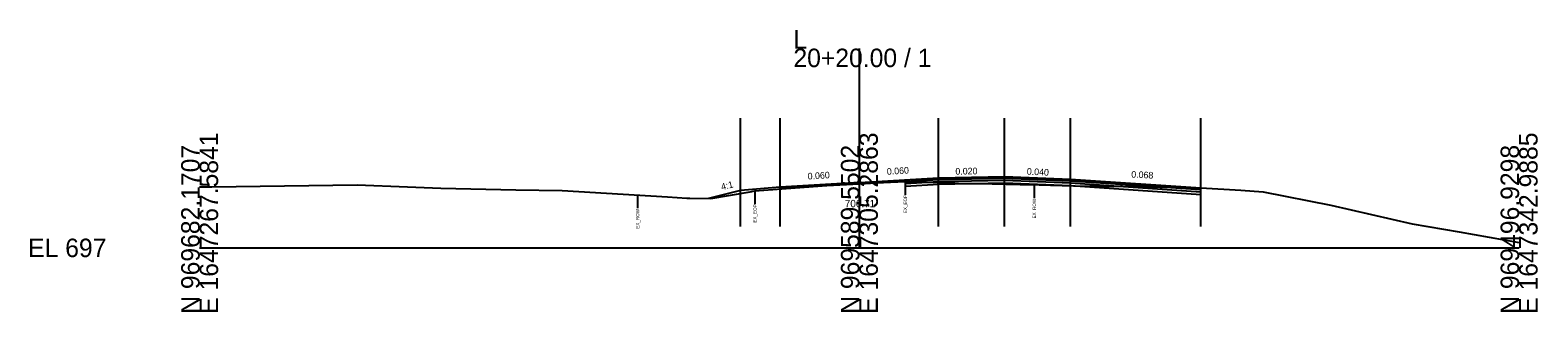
# Model space of a CAD drawing. Extents: x -26 to 2611564, y -962368 to 969476.
# Drawn here: x -25.7 to 202.8, y 10990.3 to 11033 of the extents above; entities that cross this region are included whole.
import ezdxf

# ---------------------------------------------------------------- set-up
doc = ezdxf.new("R2010")
doc.units = 0
for name, color, linetype in [('Exist Cross Section Cell', 7, 'Continuous'), ('Exist XS Center Line Elevation Label', 7, 'Continuous'), ('Exist XS Ground Line', 7, 'Continuous'), ('Pattern 5', 7, 'Continuous'), ('Pattern 7', 7, 'Continuous'), ('Prop CMT Pvmt Course 1', 7, 'Continuous'), ('Prop CMT Slope Grass', 7, 'Continuous'), ('Prop CMT Subgrade Earthwork', 7, 'Continuous'), ('Prop XS SE Text', 7, 'Continuous'), ('Prop XS Side Slope Text', 7, 'Continuous'), ('Scratch_Level_7', 7, 'Continuous')]:
    doc.layers.add(name, color=color, linetype=linetype)

msp = doc.modelspace()

# ---------------------------------------------------------------- linework, layer by layer
at = {"layer": 'Exist Cross Section Cell'}
for p, q in [((100, 11000), (100, 11030.19)), ((0, 11000), (100, 11000)), ((100, 11000), (200, 11000))]:
    msp.add_line(p, q, dxfattribs=at)
at = {"layer": 'Exist XS Ground Line'}
msp.add_lwpolyline([(0, 11009.23), (1.87, 11009.26), (23.9, 11009.54), (31.52, 11009.23), (36.57, 11009.03), (47.94, 11008.77), (54.93, 11008.67), (70.93, 11007.73), (73.86, 11007.55), (74.28, 11007.54), (77.49, 11007.49), (83.45, 11008.51), (84.16, 11008.63), (95.05, 11009.47), (100, 11009.71), (102.54, 11009.84), (106.95, 11010.06), (116.62, 11009.77), (117.67, 11009.74), (117.99, 11009.74), (124.39, 11009.58), (124.76, 11009.58), (125.11, 11009.58), (125.49, 11009.58), (132.47, 11009.41), (136.47, 11009.33), (137.58, 11009.34), (138.92, 11009.33), (139.86, 11009.33), (145.58, 11009.22), (147.26, 11009.19), (151.76, 11009.1), (157.82, 11008.76), (161.18, 11008.51), (171.44, 11006.45), (183.81, 11003.64), (190.89, 11002.43), (200, 11000.8)], dxfattribs=at)
at = {"layer": 'Pattern 5'}
for p, q in [((126.5, 11009.55), (126.5, 11007.55)), ((66.38, 11008), (66.38, 11006))]:
    msp.add_line(p, q, dxfattribs=at)
at = {"layer": 'Pattern 7'}
for p, q in [((84.17, 11008.63), (84.17, 11006.63)), ((106.96, 11010.06), (106.96, 11008.06))]:
    msp.add_line(p, q, dxfattribs=at)
at = {"layer": 'Prop CMT Pvmt Course 1'}
for p, q in [((112, 11010.63), (122, 11010.83)), ((100, 11009.91), (88, 11009.19)), ((88, 11009.19), (88, 11009.07)), ((100.01, 11009.79), (88.01, 11009.07)), ((100, 11009.91), (112, 11010.63)), ((100.01, 11009.79), (106.96, 11010.21)), ((106.96, 11010.08), (112.01, 11010.38)), ((106.96, 11009.75), (112.03, 11010.05)), ((112, 11010.38), (122, 11010.58)), ((112, 11010.05), (121.99, 11010.25))]:
    msp.add_line(p, q, dxfattribs=at)
for points in [[(122, 11010.83), (132, 11010.43), (151.76, 11009.1)], [(121.99, 11010.25), (132, 11009.85), (151.76, 11008.51)], [(122, 11010.58), (132, 11010.18), (151.76, 11008.84)]]:
    msp.add_lwpolyline(points, dxfattribs=at)
at = {"layer": 'Prop CMT Slope Grass'}
for p, q in [((82, 11008.71), (77.14, 11007.5)), ((88, 11009.19), (82, 11008.71))]:
    msp.add_line(p, q, dxfattribs=at)
at = {"layer": 'Prop CMT Subgrade Earthwork'}
for p, q in [((88, 11009.19), (88, 11008.92)), ((106.96, 11010.21), (106.96, 11009.33)), ((106.96, 11009.33), (112.06, 11009.64)), ((112, 11009.63), (121.98, 11009.83)), ((151.76, 11008.09), (151.76, 11009.1))]:
    msp.add_line(p, q, dxfattribs=at)
msp.add_lwpolyline([(121.98, 11009.83), (132, 11009.43), (151.76, 11008.09)], dxfattribs=at)
at = {"layer": 'Scratch_Level_7'}
for p, q in [((82, 11003.26), (82, 11019.67)), ((88, 11003.26), (88, 11019.67)), ((100, 11003.26), (100, 11019.67)), ((112, 11003.26), (112, 11019.67)), ((122, 11003.26), (122, 11019.67)), ((132, 11003.26), (132, 11019.67)), ((151.76, 11003.26), (151.76, 11019.67))]:
    msp.add_line(p, q, dxfattribs=at)

# ---------------------------------------------------------------- texts
at = {"layer": 'Exist Cross Section Cell'}
for s, p in [('L', (90, 11030.19)), ('20+20.00 / 1', (90, 11027.39)), ('EL 697', (-26, 10998.6))]:
    msp.add_text(s, height=2.8, dxfattribs=at).set_placement(p)
for s, p in [('N 969682.1707', (0, 10990)), ('E 1647267.5841', (2.8, 10990)), ('N 969589.5502', (100, 10990)), ('E 1647305.2863', (102.8, 10990)), ('N 969496.9298', (200, 10990)), ('E 1647342.9885', (202.8, 10990))]:
    msp.add_text(s, height=2.8, rotation=90, dxfattribs=at).set_placement(p)
at = {"layer": 'Exist XS Center Line Elevation Label'}
msp.add_text('706.71', height=1.125, dxfattribs=at).set_placement((97.79, 11006.15))
at = {"layer": 'Pattern 5'}
for p in [(126.75, 11004.45), (66.63, 11002.9)]:
    msp.add_text('EX_ROW', height=0.5, rotation=90, dxfattribs=at).set_placement(p)
at = {"layer": 'Pattern 7'}
for p in [(84.42, 11003.83), (107.21, 11005.26)]:
    msp.add_text('EX_EOP', height=0.5, rotation=90, dxfattribs=at).set_placement(p)
at = {"layer": 'Prop XS SE Text'}
for s, rotation, p in [('0.060', 3.4336, (92.19, 11010.35)), ('0.060', 3.4336, (104.19, 11011.07)), ('0.020', 1.1458, (114.56, 11011.09)), ('0.040', 357.1376, (125.36, 11011.1)), ('0.068', 357.1376, (141.19, 11010.66))]:
    msp.add_text(s, height=1, rotation=rotation, dxfattribs=at).set_placement(p)
at = {"layer": 'Prop XS Side Slope Text'}
msp.add_text('4:1', height=1, rotation=14.0363, dxfattribs=at).set_placement((79.16, 11008.73))

doc.saveas('drawing.dxf')
